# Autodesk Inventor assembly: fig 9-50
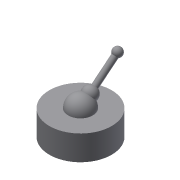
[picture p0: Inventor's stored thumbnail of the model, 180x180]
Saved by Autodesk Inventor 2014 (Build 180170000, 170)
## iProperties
Created: 2013-07
Part Number: fig 9-50
Document SubType Name: Assembly
Designer: CADCIM
Author: CADCIM
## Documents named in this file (3)
- E:\APS\Autodesk Inventor 2014-Project\inventor_2014_partfiles\Inventor_2014_prt\c09_Inv_2014_prt\c09_inv_2014_prt\fig 9-50.iam
- E:\APS\c09partfile\fig 9-49_1.ipt
- E:\APS\c09partfile\fig 9-49_2.ipt
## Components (2 placed, 2 different names)
1. fig 9-49_1:1 — Ball:1
2. fig 9-49_2:1 — Ball:1
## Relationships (1: BallJoint 1)
- Ball:1: fig 9-49_1:1 ↔ fig 9-49_2:1
